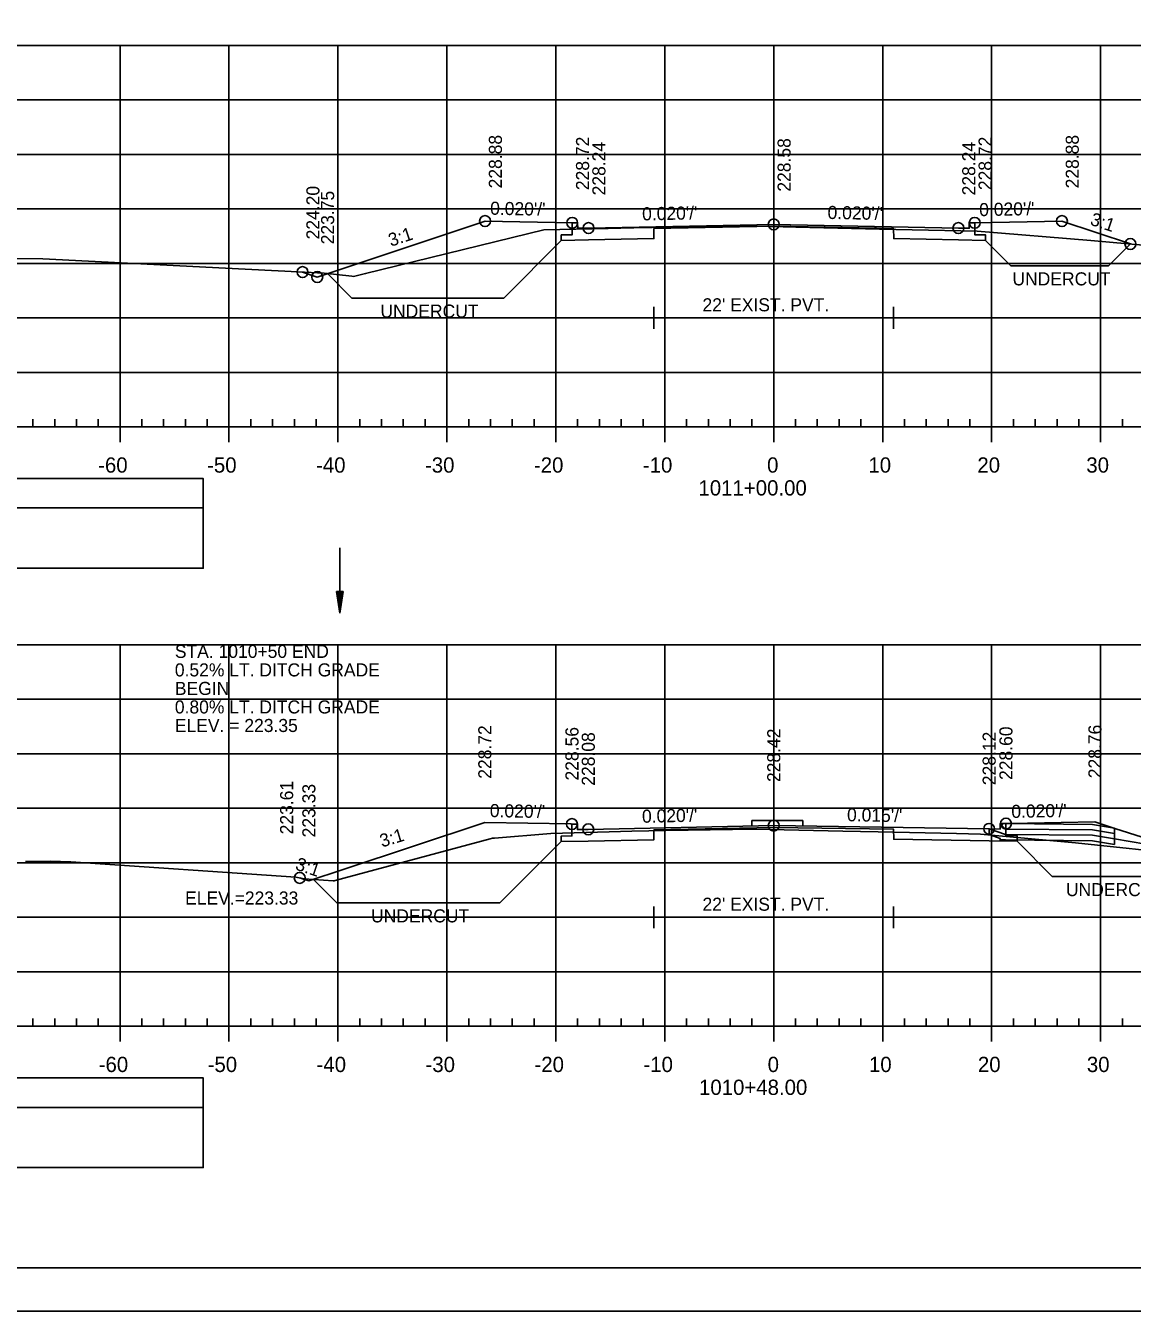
# Model space of a CAD drawing. Extents: x 1386544 to 1388153, y 379785 to 390999.
# Drawn here: x 1387297.9 to 1387399.4, y 381223.9 to 381341.8 of the extents above; entities that cross this region are included whole.
import ezdxf

# ---------------------------------------------------------------- set-up
doc = ezdxf.new("R2010")
doc.units = 0
for name, color, linetype in [('R_Alt Surface', 7, 'Continuous'), ('R_Axis', 7, 'Continuous'), ('R_Axis Annot', 7, 'Continuous'), ('R_Border', 7, 'Continuous'), ('R_Dimension', 7, 'Continuous'), ('R_Exist Surface', 7, 'Continuous'), ('R_Fin Surface', 7, 'Continuous'), ('R_Fin Surface Annot', 7, 'Continuous'), ('R_Grid', 7, 'Continuous'), ('R_No Plot', 7, 'Continuous'), ('R_Proposed Road', 7, 'Continuous'), ('R_Striping', 7, 'Continuous'), ('R_Water', 7, 'Continuous'), ('R_Xsect Elev', 7, 'Continuous'), ('R_Xsect Slope', 7, 'Continuous')]:
    doc.layers.add(name, color=color, linetype=linetype)

msp = doc.modelspace()

# ---------------------------------------------------------------- linework, layer by layer
at = {"layer": 'R_Alt Surface'}
for points in [[(1387384.96, 381323.74), (1387384.96, 381322.65), (1387385.96, 381322.63), (1387385.96, 381322.13), (1387383.46, 381322.18), (1387377.52, 381322.29), (1387377.51, 381323.21), (1387366.51, 381323.43), (1387355.51, 381323.21), (1387355.51, 381322.29), (1387349.51, 381322.18), (1387347.01, 381322.13), (1387347.01, 381322.63), (1387348.01, 381322.65), (1387348.01, 381323.74)], [(1387355.51, 381316.02), (1387355.51, 381314.02)], [(1387377.51, 381316.02), (1387377.51, 381314.02)], [(1387355.51, 381315.02), (1387377.51, 381315.02)], [(1387387.82, 381268.62), (1387387.82, 381267.52), (1387388.84, 381267.5), (1387388.84, 381267), (1387386.28, 381267.05), (1387377.52, 381267.18), (1387377.51, 381268.1), (1387366.51, 381268.26), (1387355.51, 381268.04), (1387355.51, 381267.13), (1387349.49, 381267.01), (1387346.99, 381266.96), (1387346.99, 381267.46), (1387347.99, 381267.48), (1387347.99, 381268.57)], [(1387355.51, 381261.02), (1387355.51, 381259.02)], [(1387377.51, 381261.02), (1387377.51, 381259.02)], [(1387355.51, 381260.02), (1387377.51, 381260.02)]]:
    msp.add_lwpolyline(points, dxfattribs=at)
at = {"layer": 'R_Axis'}
for p, q in [((1387221.51, 381305.02), (1387511.51, 381305.02)), ((1387298.51, 381305.02), (1387298.51, 381305.72)), ((1387300.51, 381305.02), (1387300.51, 381305.72)), ((1387302.51, 381305.02), (1387302.51, 381305.72)), ((1387304.51, 381305.02), (1387304.51, 381305.72)), ((1387306.51, 381303.62), (1387306.51, 381305.02)), ((1387308.51, 381305.02), (1387308.51, 381305.72)), ((1387310.51, 381305.02), (1387310.51, 381305.72)), ((1387312.51, 381305.02), (1387312.51, 381305.72)), ((1387314.51, 381305.02), (1387314.51, 381305.72)), ((1387316.51, 381303.62), (1387316.51, 381305.02)), ((1387318.51, 381305.02), (1387318.51, 381305.72)), ((1387320.51, 381305.02), (1387320.51, 381305.72)), ((1387322.51, 381305.02), (1387322.51, 381305.72)), ((1387324.51, 381305.02), (1387324.51, 381305.72)), ((1387326.51, 381303.62), (1387326.51, 381305.02)), ((1387328.51, 381305.02), (1387328.51, 381305.72)), ((1387330.51, 381305.02), (1387330.51, 381305.72)), ((1387332.51, 381305.02), (1387332.51, 381305.72)), ((1387334.51, 381305.02), (1387334.51, 381305.72)), ((1387336.51, 381303.62), (1387336.51, 381305.02)), ((1387338.51, 381305.02), (1387338.51, 381305.72)), ((1387340.51, 381305.02), (1387340.51, 381305.72)), ((1387342.51, 381305.02), (1387342.51, 381305.72)), ((1387344.51, 381305.02), (1387344.51, 381305.72)), ((1387346.51, 381303.62), (1387346.51, 381305.02)), ((1387348.51, 381305.02), (1387348.51, 381305.72)), ((1387350.51, 381305.02), (1387350.51, 381305.72)), ((1387352.51, 381305.02), (1387352.51, 381305.72)), ((1387354.51, 381305.02), (1387354.51, 381305.72)), ((1387356.51, 381303.62), (1387356.51, 381305.02)), ((1387358.51, 381305.02), (1387358.51, 381305.72)), ((1387360.51, 381305.02), (1387360.51, 381305.72)), ((1387362.51, 381305.02), (1387362.51, 381305.72)), ((1387364.51, 381305.02), (1387364.51, 381305.72)), ((1387366.51, 381303.62), (1387366.51, 381305.02)), ((1387368.51, 381305.02), (1387368.51, 381305.72)), ((1387370.51, 381305.02), (1387370.51, 381305.72)), ((1387372.51, 381305.02), (1387372.51, 381305.72)), ((1387374.51, 381305.02), (1387374.51, 381305.72)), ((1387376.51, 381303.62), (1387376.51, 381305.02)), ((1387378.51, 381305.02), (1387378.51, 381305.72)), ((1387380.51, 381305.02), (1387380.51, 381305.72)), ((1387382.51, 381305.02), (1387382.51, 381305.72)), ((1387384.51, 381305.02), (1387384.51, 381305.72)), ((1387386.51, 381303.62), (1387386.51, 381305.02)), ((1387388.51, 381305.02), (1387388.51, 381305.72)), ((1387390.51, 381305.02), (1387390.51, 381305.72)), ((1387392.51, 381305.02), (1387392.51, 381305.72)), ((1387394.51, 381305.02), (1387394.51, 381305.72)), ((1387396.51, 381303.62), (1387396.51, 381305.02)), ((1387398.51, 381305.02), (1387398.51, 381305.72)), ((1387221.51, 381250.02), (1387511.51, 381250.02)), ((1387298.51, 381250.02), (1387298.51, 381250.72)), ((1387300.51, 381250.02), (1387300.51, 381250.72)), ((1387302.51, 381250.02), (1387302.51, 381250.72)), ((1387304.51, 381250.02), (1387304.51, 381250.72)), ((1387306.51, 381248.62), (1387306.51, 381250.02)), ((1387308.51, 381250.02), (1387308.51, 381250.72)), ((1387310.51, 381250.02), (1387310.51, 381250.72)), ((1387312.51, 381250.02), (1387312.51, 381250.72)), ((1387314.51, 381250.02), (1387314.51, 381250.72)), ((1387316.51, 381248.62), (1387316.51, 381250.02)), ((1387318.51, 381250.02), (1387318.51, 381250.72)), ((1387320.51, 381250.02), (1387320.51, 381250.72)), ((1387322.51, 381250.02), (1387322.51, 381250.72)), ((1387324.51, 381250.02), (1387324.51, 381250.72)), ((1387326.51, 381248.62), (1387326.51, 381250.02)), ((1387328.51, 381250.02), (1387328.51, 381250.72)), ((1387330.51, 381250.02), (1387330.51, 381250.72)), ((1387332.51, 381250.02), (1387332.51, 381250.72)), ((1387334.51, 381250.02), (1387334.51, 381250.72)), ((1387336.51, 381248.62), (1387336.51, 381250.02)), ((1387338.51, 381250.02), (1387338.51, 381250.72)), ((1387340.51, 381250.02), (1387340.51, 381250.72)), ((1387342.51, 381250.02), (1387342.51, 381250.72)), ((1387344.51, 381250.02), (1387344.51, 381250.72)), ((1387346.51, 381248.62), (1387346.51, 381250.02)), ((1387348.51, 381250.02), (1387348.51, 381250.72)), ((1387350.51, 381250.02), (1387350.51, 381250.72)), ((1387352.51, 381250.02), (1387352.51, 381250.72)), ((1387354.51, 381250.02), (1387354.51, 381250.72)), ((1387356.51, 381248.62), (1387356.51, 381250.02)), ((1387358.51, 381250.02), (1387358.51, 381250.72)), ((1387360.51, 381250.02), (1387360.51, 381250.72)), ((1387362.51, 381250.02), (1387362.51, 381250.72)), ((1387364.51, 381250.02), (1387364.51, 381250.72)), ((1387366.51, 381248.62), (1387366.51, 381250.02)), ((1387368.51, 381250.02), (1387368.51, 381250.72)), ((1387370.51, 381250.02), (1387370.51, 381250.72)), ((1387372.51, 381250.02), (1387372.51, 381250.72)), ((1387374.51, 381250.02), (1387374.51, 381250.72)), ((1387376.51, 381248.62), (1387376.51, 381250.02)), ((1387378.51, 381250.02), (1387378.51, 381250.72)), ((1387380.51, 381250.02), (1387380.51, 381250.72)), ((1387382.51, 381250.02), (1387382.51, 381250.72)), ((1387384.51, 381250.02), (1387384.51, 381250.72)), ((1387386.51, 381248.62), (1387386.51, 381250.02)), ((1387388.51, 381250.02), (1387388.51, 381250.72)), ((1387390.51, 381250.02), (1387390.51, 381250.72)), ((1387392.51, 381250.02), (1387392.51, 381250.72)), ((1387394.51, 381250.02), (1387394.51, 381250.72)), ((1387396.51, 381248.62), (1387396.51, 381250.02)), ((1387398.51, 381250.02), (1387398.51, 381250.72))]:
    msp.add_line(p, q, dxfattribs=at)
at = {"layer": 'R_Border'}
msp.add_line((1387524.69, 381227.85), (1387208.51, 381227.85), dxfattribs=at)
at = {"layer": 'R_Dimension'}
for p, q in [((1387347.01, 381322.13), (1387341.73, 381316.84)), ((1387385.96, 381322.13), (1387388.28, 381319.8)), ((1387399.25, 381321.8), (1387397.25, 381319.8)), ((1387325.56, 381319.08), (1387327.8, 381316.84)), ((1387346.99, 381266.96), (1387341.38, 381261.35)), ((1387388.84, 381267), (1387392.08, 381263.76)), ((1387324.27, 381263.5), (1387326.42, 381261.35))]:
    msp.add_line(p, q, dxfattribs=at)
for points in [[(1387397.25, 381319.8), (1387388.28, 381319.8)], [(1387327.8, 381316.84), (1387341.73, 381316.84)], [(1387403.28, 381263.76), (1387392.08, 381263.76)], [(1387326.42, 381261.35), (1387341.38, 381261.35)]]:
    msp.add_lwpolyline(points, dxfattribs=at)
at = {"layer": 'R_Exist Surface'}
for points in [[(1387221.51, 381321.36), (1387258.57, 381320.88), (1387269.01, 381320.75), (1387275.68, 381320.67), (1387281.2, 381320.6), (1387299.43, 381320.45), (1387316.2, 381319.58), (1387325.24, 381319.12), (1387327.78, 381318.84), (1387327.94, 381318.83), (1387329.04, 381319.08), (1387345.4, 381323.09), (1387351.31, 381323.22), (1387353.66, 381323.29), (1387357.07, 381323.33), (1387365.05, 381323.42), (1387368.54, 381323.34), (1387376.22, 381323.16), (1387379.22, 381323.1), (1387385.19, 381322.99), (1387395.6, 381322.13), (1387400.74, 381321.67)], [(1387297.82, 381265.15), (1387300.12, 381265.16), (1387301.99, 381265.11), (1387322.66, 381263.69), (1387323.42, 381263.56), (1387326.08, 381263.36), (1387326.16, 381263.35), (1387326.26, 381263.39), (1387340.47, 381267.22), (1387340.7, 381267.28), (1387340.87, 381267.29), (1387346.05, 381267.72), (1387351.39, 381267.86), (1387353.48, 381267.93), (1387356.6, 381267.98), (1387364.76, 381268.11), (1387372.86, 381267.92), (1387376.1, 381267.85), (1387383.29, 381267.7), (1387385.5, 381267.65), (1387394.2, 381266.84), (1387404.65, 381265.76)]]:
    msp.add_lwpolyline(points, dxfattribs=at)
at = {"layer": 'R_Fin Surface'}
for points in [[(1387323.26, 381319.22), (1387324.61, 381318.77), (1387340.01, 381323.9), (1387348.01, 381323.74), (1387348.51, 381323.74), (1387348.52, 381323.24), (1387349.51, 381323.26), (1387366.51, 381323.6), (1387383.46, 381323.26), (1387384.46, 381323.24), (1387384.46, 381323.74), (1387384.96, 381323.74), (1387392.96, 381323.9), (1387399.25, 381321.8)], [(1387323, 381263.63), (1387323.25, 381263.55), (1387323.84, 381263.35), (1387327, 381264.41), (1387339.99, 381268.73), (1387347.88, 381268.58), (1387347.99, 381268.57), (1387348, 381268.57), (1387348.49, 381268.57), (1387348.49, 381268.57), (1387348.49, 381268.07), (1387349.49, 381268.09), (1387366.51, 381268.43), (1387386.28, 381268.14), (1387387.3, 381268.12), (1387387.3, 381268.59), (1387387.3, 381268.62), (1387387.77, 381268.62), (1387387.82, 381268.62), (1387389.8, 381268.66), (1387395.99, 381268.78), (1387397.82, 381268.18), (1387400.32, 381267.37)]]:
    msp.add_lwpolyline(points, dxfattribs=at)
at = {"layer": 'R_Grid'}
for p, q in [((1387221.51, 381340.02), (1387511.51, 381340.02)), ((1387306.51, 381305.02), (1387306.51, 381340.02)), ((1387316.51, 381305.02), (1387316.51, 381340.02)), ((1387326.51, 381305.02), (1387326.51, 381340.02)), ((1387336.51, 381305.02), (1387336.51, 381340.02)), ((1387346.51, 381305.02), (1387346.51, 381340.02)), ((1387356.51, 381305.02), (1387356.51, 381340.02)), ((1387366.51, 381305.02), (1387366.51, 381340.02)), ((1387376.51, 381305.02), (1387376.51, 381340.02)), ((1387386.51, 381305.02), (1387386.51, 381340.02)), ((1387396.51, 381305.02), (1387396.51, 381340.02)), ((1387221.51, 381335.02), (1387511.51, 381335.02)), ((1387221.51, 381335.02), (1387511.51, 381335.02)), ((1387306.51, 381305.02), (1387306.51, 381335.02)), ((1387316.51, 381305.02), (1387316.51, 381335.02)), ((1387326.51, 381305.02), (1387326.51, 381335.02)), ((1387336.51, 381305.02), (1387336.51, 381335.02)), ((1387346.51, 381305.02), (1387346.51, 381335.02)), ((1387356.51, 381305.02), (1387356.51, 381335.02)), ((1387366.51, 381305.02), (1387366.51, 381335.02)), ((1387376.51, 381305.02), (1387376.51, 381335.02)), ((1387386.51, 381305.02), (1387386.51, 381335.02)), ((1387396.51, 381305.02), (1387396.51, 381335.02)), ((1387221.51, 381330.02), (1387511.51, 381330.02)), ((1387221.51, 381330.02), (1387511.51, 381330.02)), ((1387221.51, 381325.02), (1387511.51, 381325.02)), ((1387221.51, 381325.02), (1387511.51, 381325.02)), ((1387221.51, 381320.02), (1387511.51, 381320.02)), ((1387221.51, 381320.02), (1387511.51, 381320.02)), ((1387221.51, 381315.02), (1387511.51, 381315.02)), ((1387221.51, 381315.02), (1387511.51, 381315.02)), ((1387221.51, 381310.02), (1387511.51, 381310.02)), ((1387221.51, 381310.02), (1387511.51, 381310.02)), ((1387221.51, 381305.02), (1387511.51, 381305.02)), ((1387221.51, 381305.02), (1387511.51, 381305.02)), ((1387221.51, 381285.02), (1387511.51, 381285.02)), ((1387306.51, 381250.02), (1387306.51, 381285.02)), ((1387316.51, 381250.02), (1387316.51, 381285.02)), ((1387326.51, 381250.02), (1387326.51, 381285.02)), ((1387336.51, 381250.02), (1387336.51, 381285.02)), ((1387346.51, 381250.02), (1387346.51, 381285.02)), ((1387356.51, 381250.02), (1387356.51, 381285.02)), ((1387366.51, 381250.02), (1387366.51, 381285.02)), ((1387376.51, 381250.02), (1387376.51, 381285.02)), ((1387386.51, 381250.02), (1387386.51, 381285.02)), ((1387396.51, 381250.02), (1387396.51, 381285.02)), ((1387221.51, 381280.02), (1387511.51, 381280.02)), ((1387221.51, 381275.02), (1387511.51, 381275.02)), ((1387221.51, 381270.02), (1387511.51, 381270.02)), ((1387221.51, 381265.02), (1387511.51, 381265.02)), ((1387221.51, 381260.02), (1387511.51, 381260.02)), ((1387221.51, 381255.02), (1387511.51, 381255.02)), ((1387221.51, 381250.02), (1387511.51, 381250.02))]:
    msp.add_line(p, q, dxfattribs=at)
at = {"layer": 'R_No Plot'}
msp.add_line((1387196.11, 381223.87), (1387529.45, 381223.87), dxfattribs=at)
for points in [[(1387196.11, 381437.2), (1387529.45, 381437.2), (1387529.45, 381223.87), (1387196.11, 381223.87)], [(1387442.43, 381433.31), (1387462.05, 381433.31), (1387462.05, 381423.43), (1387478.17, 381423.43), (1387501.37, 381423.43), (1387501.37, 381399.1), (1387524.69, 381399.1), (1387524.69, 381227.85), (1387208.51, 381227.85), (1387208.51, 381433.31)]]:
    msp.add_lwpolyline(points, close=True, dxfattribs=at)
for centre in [(1387340.01, 381323.9), (1387348.01, 381323.74), (1387366.51, 381323.6), (1387384.96, 381323.74), (1387392.96, 381323.9), (1387349.51, 381323.26), (1387383.46, 381323.26), (1387399.25, 381321.8), (1387323.26, 381319.22), (1387324.61, 381318.77), (1387347.99, 381268.57), (1387349.49, 381268.09), (1387366.51, 381268.43), (1387386.28, 381268.14), (1387387.82, 381268.62), (1387323, 381263.63)]:
    msp.add_circle(centre, 0.5, dxfattribs=at)
at = {"layer": 'R_Proposed Road'}
for p, q in [((1387364.51, 381268.39), (1387364.51, 381268.89)), ((1387364.51, 381268.89), (1387369.19, 381268.89)), ((1387369.19, 381268.39), (1387369.19, 381268.89))]:
    msp.add_line(p, q, dxfattribs=at)
at = {"layer": 'R_Striping'}
for points in [[(1387285.95, 381297.58), (1387314.14, 381297.58), (1387314.14, 381300.28), (1387285.95, 381300.28)], [(1387285.95, 381292.05), (1387314.14, 381292.05), (1387314.14, 381297.58), (1387285.95, 381297.58)], [(1387285.95, 381242.58), (1387314.14, 381242.58), (1387314.14, 381245.28), (1387285.95, 381245.28)], [(1387285.95, 381237.05), (1387314.14, 381237.05), (1387314.14, 381242.58), (1387285.95, 381242.58)]]:
    msp.add_lwpolyline(points, close=True, dxfattribs=at)
at = {"layer": 'R_Water'}
for p, q in [((1387326.69, 381293.92), (1387326.69, 381287.92)), ((1387326.39, 381289.92), (1387326.69, 381287.92)), ((1387326.99, 381289.92), (1387326.39, 381289.92)), ((1387326.39, 381289.92), (1387326.69, 381287.92)), ((1387326.99, 381289.92), (1387326.39, 381289.92)), ((1387326.44, 381289.92), (1387326.69, 381288.25)), ((1387326.44, 381289.92), (1387326.69, 381288.25)), ((1387326.49, 381289.92), (1387326.69, 381288.6)), ((1387326.49, 381289.92), (1387326.69, 381288.6)), ((1387326.54, 381289.92), (1387326.69, 381288.93)), ((1387326.54, 381289.92), (1387326.69, 381288.93)), ((1387326.59, 381289.92), (1387326.69, 381289.27)), ((1387326.59, 381289.92), (1387326.69, 381289.27)), ((1387326.64, 381289.92), (1387326.69, 381289.6)), ((1387326.64, 381289.92), (1387326.69, 381289.6)), ((1387326.99, 381289.92), (1387326.69, 381287.92)), ((1387326.79, 381289.92), (1387326.69, 381289.27)), ((1387326.89, 381289.92), (1387326.69, 381288.6)), ((1387326.94, 381289.92), (1387326.69, 381288.25)), ((1387326.84, 381289.92), (1387326.69, 381288.93)), ((1387326.74, 381289.92), (1387326.69, 381289.6)), ((1387326.99, 381289.92), (1387326.69, 381287.92)), ((1387326.79, 381289.92), (1387326.69, 381289.27)), ((1387326.89, 381289.92), (1387326.69, 381288.6)), ((1387326.94, 381289.92), (1387326.69, 381288.25)), ((1387326.84, 381289.92), (1387326.69, 381288.93)), ((1387326.74, 381289.92), (1387326.69, 381289.6)), ((1387387.78, 381268.62), (1387395.78, 381268.54)), ((1387395.78, 381268.54), (1387397.78, 381268.21)), ((1387387.78, 381268.12), (1387395.78, 381268.04)), ((1387387.78, 381267.62), (1387395.78, 381267.54)), ((1387395.78, 381268.04), (1387397.78, 381267.71)), ((1387395.78, 381267.54), (1387397.78, 381267.21)), ((1387397.78, 381266.71), (1387397.78, 381268.21)), ((1387387.78, 381267.12), (1387395.78, 381267.04)), ((1387395.78, 381267.04), (1387397.78, 381266.71)), ((1387397.78, 381267.21), (1387403.22, 381266.3))]:
    msp.add_line(p, q, dxfattribs=at)
for points in [[(1387387.78, 381268.62), (1387387.53, 381268.62), (1387387.45, 381268.45), (1387387.78, 381268.12)], [(1387387.78, 381267.62), (1387386.28, 381268.14), (1387386.28, 381267.61), (1387387.28, 381267.26), (1387387.28, 381267.12), (1387387.78, 381267.12)]]:
    msp.add_lwpolyline(points, dxfattribs=at)

# ---------------------------------------------------------------- texts
at = {"layer": 'R_Axis Annot'}
for s, p in [('-60', (1387304.5, 381300.82)), ('-50', (1387314.5, 381300.82)), ('-40', (1387324.5, 381300.82)), ('-30', (1387334.5, 381300.82)), ('-20', (1387344.5, 381300.82)), ('-10', (1387354.5, 381300.82)), ('0', (1387365.9, 381300.82)), ('10', (1387375.2, 381300.82)), ('20', (1387385.2, 381300.82)), ('30', (1387395.2, 381300.82)), ('1011+00.00', (1387359.6, 381298.72)), ('-60', (1387304.55, 381245.82)), ('-50', (1387314.55, 381245.82)), ('-40', (1387324.55, 381245.82)), ('-30', (1387334.55, 381245.82)), ('-20', (1387344.55, 381245.82)), ('-10', (1387354.55, 381245.82)), ('0', (1387365.95, 381245.82)), ('10', (1387375.25, 381245.82)), ('20', (1387385.25, 381245.82)), ('30', (1387395.25, 381245.82)), ('1010+48.00', (1387359.65, 381243.72))]:
    msp.add_text(s, height=1.4, dxfattribs=at).set_placement(p)
at = {"layer": 'R_Dimension'}
for p in [(1387388.42, 381318), (1387330.41, 381315.04), (1387393.33, 381261.96), (1387329.55, 381259.55)]:
    msp.add_text('UNDERCUT', height=1.2, dxfattribs=at).set_placement(p)
at = {"layer": 'R_Fin Surface Annot'}
for s, p in [('STA. 1010+50 END', (1387311.54, 381283.82)), ('0.52% LT. DITCH GRADE', (1387311.54, 381282.12)), ('BEGIN', (1387311.54, 381280.42)), ('0.80% LT. DITCH GRADE', (1387311.54, 381278.72)), ('ELEV. = 223.35', (1387311.54, 381277.02)), ('ELEV.=223.33', (1387312.48, 381261.19))]:
    msp.add_text(s, height=1.2, dxfattribs=at).set_placement(p)
for s, rotation, p in [('228.72', 90, (1387340.59, 381272.73)), ('228.56', 90, (1387348.59, 381272.57)), ('228.08', 90, (1387350.09, 381272.09)), ('228.42', 90, (1387367.11, 381272.43)), ('228.12', 90, (1387386.88, 381272.14)), ('228.60', 90, (1387388.42, 381272.62)), ('228.76', 90, (1387396.59, 381272.78)), ('223.61', 90, (1387322.4, 381267.63)), ('223.33', 90, (1387324.44, 381267.35)), ("0.020'/'", 358.8591, (1387340.44, 381269.22)), ("0.020'/'", 1.1434, (1387354.43, 381268.69)), ("0.015'/'", 359.1443, (1387373.23, 381268.83)), ("0.020'/'", 1.1235, (1387388.33, 381269.13)), ('3:1', 16.7132, (1387330.55, 381266.42)), ('3:1', 341.5651, (1387322.52, 381264.42))]:
    msp.add_text(s, height=1.2, rotation=rotation, dxfattribs=at).set_placement(p)
at = {"layer": 'R_No Plot'}
for p in [(1387339.94, 381268.68), (1387395.95, 381268.73)]:
    msp.add_text('+', height=0.1, dxfattribs=at).set_placement(p)
at = {"layer": 'R_Water'}
for p in [(1387359.97, 381315.62), (1387359.97, 381260.62)]:
    msp.add_text("22' EXIST. PVT.", height=1.2, dxfattribs=at).set_placement(p)
at = {"layer": 'R_Xsect Elev'}
for s, p in [('228.88', (1387341.56, 381326.9)), ('228.72', (1387349.56, 381326.74)), ('228.24', (1387351.06, 381326.26)), ('228.58', (1387368.06, 381326.6)), ('228.24', (1387385.01, 381326.26)), ('228.72', (1387386.51, 381326.74)), ('228.88', (1387394.51, 381326.9)), ('224.20', (1387324.81, 381322.22)), ('223.75', (1387326.16, 381321.77))]:
    msp.add_text(s, height=1.2, rotation=90, dxfattribs=at).set_placement(p)
at = {"layer": 'R_Xsect Slope'}
for s, rotation, p in [("0.020'/'", 358.8542, (1387340.47, 381324.49)), ("0.020'/'", 1.1458, (1387354.44, 381323.96)), ("0.020'/'", 358.8542, (1387371.44, 381324.1)), ("0.020'/'", 1.1458, (1387385.38, 381324.35)), ('3:1', 341.5651, (1387395.47, 381323.59)), ('3:1', 18.4349, (1387331.37, 381321.54))]:
    msp.add_text(s, height=1.2, rotation=rotation, dxfattribs=at).set_placement(p)

doc.saveas('drawing.dxf')
